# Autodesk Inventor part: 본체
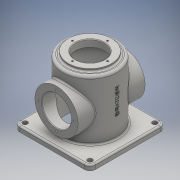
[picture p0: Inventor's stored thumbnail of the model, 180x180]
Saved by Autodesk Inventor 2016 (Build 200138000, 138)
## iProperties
Created: 2019-08
Part Number: 본체
Material: 일반
Document SubType Name: Modeling
Designer: user
Density: 1 g/cm^3
Appearance: 기본값
Author: user
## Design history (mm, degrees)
sketch "스케치1"
  geometry: L1 (-70, 70)-(70, 70); L2 (70, 70)-(70, -70); L3 (70, -70)-(-70, -70); L4 (-70, -70)-(-70, 70); L5 (-70, 70)-(70, -70); L6 (70, 70)-(-70, -70); 1 further point
  constraints: 12 end point, 2 midpoint, 2 parallel, 1 horizontal, 1 perpendicular
  dimensions: "d0" = 140 distance of L2.end L3.end; "d1" = 140 distance of L1.end L2.end
extrude "돌출1" new body sketch "스케치1" distance "d2" = 10; taper "d3" = 0 deg
sketch "스케치2"
  geometry: C1 r 50 at (0, 0); 1 further point
  constraints: 1 centre point, 1 coincident
  dimensions: "d4" = 100 diameter of C1
extrude "돌출2" join sketch "스케치2" distance "d5" = 110; taper "d6" = 0 deg
sketch "스케치5"
  geometry: C1 r 45 at (0, 0); 1 further point
  constraints: 1 centre point, 1 coincident
  dimensions: "d15" = 90 diameter of C1
extrude "돌출4" cut sketch "스케치5" distance "d16" = 112; taper "d17" = 0 deg
node "작업 평면3"
sketch "스케치6"
  geometry: L1 (-70, 0)-(70, 0) reference; C1 r 40 at (0, 60); 3 further points
  constraints: 2 midpoint, 1 centre point, 1 vertical alignment
  dimensions: "d20" = 80 diameter of C1; "d21" = 60 distance from line of C1.centre L1
extrude "돌출5" join sketch "스케치6" stored distance "d22" = 112; taper "d23" = 0 deg
hole "구멍1" diameter "d26" = 54; stored, may be unused: countersink angle "d30" = 90 deg, drill point angle "d32" = 118 deg; dims "d24" = 10, "d25" = 10, "d27" = 6, "d28" = 4, "d29" = 2, "d31" = 8
sketch "스케치9"
  geometry: L1 (70, -60)-(-70, -60) reference; 3 further points
  constraints: 1 midpoint, 1 vertical alignment
  dimensions: "d35" = 92.5 distance from line of L1 point (0, 32.5)
hole "구멍2" sketch "스케치9" at (0, 32.5) diameter "d36" = 3.242; stored, may be unused: countersink angle "d40" = 90 deg, drill point angle "d42" = 118 deg; dims "d37" = 8, "d38" = 4, "d39" = 2, "d41" = 10
sketch "스케치10"
  geometry: C1 r 40 at (0, 0); 1 further point
  constraints: 1 centre point, 1 coincident
  dimensions: "d46" = 80 diameter of C1
extrude "돌출6" join sketch "스케치10" distance "d47" = 5; taper "d48" = 0 deg
hole "구멍3" diameter "d51" = 54; stored, may be unused: countersink angle "d55" = 90 deg, drill point angle "d57" = 118 deg; dims "d49" = 10, "d50" = 10, "d52" = 8, "d53" = 4, "d54" = 2, "d56" = 13
sketch "스케치11"
  geometry: 2 further points
  constraints: 1 vertical alignment
  dimensions: "d58" = 32.5 distance of point (0, 0) point (0, 32.5)
hole "구멍4" sketch "스케치11" at (0, 32.5) diameter "d59" = 3.242; stored, may be unused: countersink angle "d63" = 90 deg, drill point angle "d65" = 118 deg; dims "d60" = 8, "d61" = 4, "d62" = 2, "d64" = 10
fillet "모깎기1" dims "d69" = 10
hole "구멍5" diameter "d72" = 9; stored, may be unused: countersink angle "d76" = 90 deg, drill point angle "d78" = 0 deg; dims "d70" = 10, "d71" = 10, "d73" = 8, "d74" = 4, "d75" = 2, "d77" = 10
fillet "모깎기2" dims "d85" = 5
fillet "모깎기3" dims "d86" = 3
fillet "모깎기4" dims "d87" = 3
chamfer "모따기1" distance "d88" = 1; stored, may be unused: second distance "d89" = 2, angle "d90" = 45 deg
fillet "모깎기5" dims "d91" = 3
fillet "모깎기6" dims "d92" = 3
node "작업 평면4"
chamfer "모따기2" distance "d97" = 1; stored, may be unused: second distance "d98" = 2, angle "d99" = 45 deg
sketch "스케치13" dims "d0" = 140, "d1" = 140
  geometry: L1 (60, 0)-(-60, 0) reference; 3 further points
  constraints: 1 midpoint, 1 vertical alignment, 1 other
  dimensions: "d100" = 70 distance from line of point (0, 70) L1
feature "엠보싱2" sketch "스케치13" dims "d0" = 140, "d1" = 140, "d101" = 0.5, "d102" = 0
node "솔리드1"
mirror "대칭1"
pattern_circular "원형 패턴1" dims angle "d44" = 360 deg
mirror "대칭2"
pattern_circular "원형 패턴2" dims angle "d67" = 360 deg
pattern_linear "직사각형 패턴1" dims "d81" = 120
other parameters: "d18" = -62
